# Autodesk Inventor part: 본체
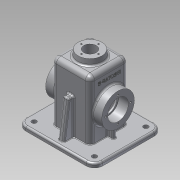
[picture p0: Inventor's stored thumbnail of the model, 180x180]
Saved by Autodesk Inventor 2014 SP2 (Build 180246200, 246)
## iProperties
Created: 2016-08
Part Number: 본체
Material: 알루미늄 6061
Document SubType Name: Modeling
Designer: user
Density: 2.71 g/cm^3
Appearance: 알루미늄 - 평지
Author: user
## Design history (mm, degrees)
sketch "스케치4"
  geometry: L1 (-65, 57.5)-(65, 57.5); L2 (65, 57.5)-(65, -57.5); L3 (65, -57.5)-(-65, -57.5); L4 (-65, -57.5)-(-65, 57.5); L5 (-65, 57.5)-(65, -57.5); L6 (65, 57.5)-(-65, -57.5); 1 further point
  constraints: 12 end point, 2 midpoint, 2 parallel, 1 horizontal, 1 perpendicular
  dimensions: "d11" = 130 distance of L1.start L1.end; "d12" = 115 distance of L1.end L2.end
extrude "돌출3" new body sketch "스케치4" distance "d13" = 10; taper "d14" = 0 deg
sketch "스케치5"
  geometry: L1 (-32.5, -32.5)-(32.5, -32.5); L2 (32.5, -32.5)-(32.5, 32.5); L3 (32.5, 32.5)-(-32.5, 32.5); L4 (-32.5, 32.5)-(-32.5, -32.5); L5 (-32.5, -32.5)-(32.5, 32.5); L6 (32.5, -32.5)-(-32.5, 32.5); 1 further point
  constraints: 12 end point, 2 midpoint, 2 parallel, 1 horizontal, 1 perpendicular
  dimensions: "d15" = 65 distance of L3.end L2.end; "d16" = 65 distance of L2.end L1.end
extrude "돌출4" join sketch "스케치5" distance "d17" = 100; taper "d18" = 0 deg
sketch "스케치6"
  geometry: L1 (0, 110)-(0, 120); L2 (0, 120)-(-20, 120); L3 (-20, 120)-(-21.228, 110); L4 (-32.5, 110)-(32.5, 110) reference; L5 (65, 0)-(-65, 0) reference; 1 further point
  constraints: 6 end point, 1 midpoint, 1 perpendicular, 1 point on line, 1 vertical
  dimensions: "d19" = 20 distance of L1.end L2.end; "d20" = 97 deg angle of L4 L3; "d21" = 120 distance between parallel lines of L5 L2
revolve "회전1" sketch "스케치6" stored, may be unused: angle "d22" = 90 deg
sketch "스케치7"
  geometry: C1 r 27.5 at (0, 55); 1 further point
  constraints: 1 centre point, 1 vertical alignment
  dimensions: "d23" = 55 diameter of C1; "d24" = 55 distance of point (0, 0) C1.centre
extrude "돌출5" join sketch "스케치7" stored distance "d25" = 95; taper "d26" = 0 deg
sketch "스케치8"
  geometry: L1 (27.5, -27.5)-(-27.5, -27.5); L2 (-27.5, -27.5)-(-27.5, 27.5); L3 (-27.5, 27.5)-(27.5, 27.5); L4 (27.5, 27.5)-(27.5, -27.5); L5 (27.5, -27.5)-(-27.5, 27.5); L6 (-27.5, -27.5)-(27.5, 27.5); 1 further point
  constraints: 12 end point, 2 midpoint, 2 parallel, 1 horizontal, 1 perpendicular
  dimensions: "d27" = 55 distance of L2.end L3.end; "d28" = 55 distance of L1.end L2.end
extrude "돌출6" cut sketch "스케치8" distance "d29" = 105; taper "d30" = 0 deg
hole "구멍1" diameter "d33" = 21; stored, may be unused: countersink angle "d37" = 90 deg, drill point angle "d39" = 118 deg; dims "d31" = 10, "d32" = 10, "d34" = 6, "d35" = 4, "d36" = 2, "d38" = 8
hole "구멍2" diameter "d42" = 35; stored, may be unused: countersink angle "d46" = 90 deg, drill point angle "d48" = 0 deg; dims "d43" = 6, "d44" = 4, "d45" = 2, "d47" = 17, "d58" = 10, "d59" = 10
hole "구멍3" diameter "d51" = 35; stored, may be unused: countersink angle "d55" = 90 deg, drill point angle "d57" = 0 deg; dims "d52" = 6, "d53" = 4, "d54" = 2, "d56" = 17, "d60" = 10, "d61" = 10
hole "구멍4" diameter "d64" = 30; stored, may be unused: countersink angle "d68" = 90 deg, drill point angle "d70" = 118 deg; dims "d62" = 10, "d63" = 10, "d65" = 6, "d66" = 4, "d67" = 2, "d69" = 3
hole "구멍5" diameter "d73" = 30; stored, may be unused: countersink angle "d77" = 90 deg, drill point angle "d79" = 118 deg; dims "d71" = 10, "d72" = 10, "d74" = 6, "d75" = 4, "d76" = 2, "d78" = 3
sketch "스케치9"
  geometry: 5 further points
  constraints: 1 horizontal alignment, 1 vertical alignment
  dimensions: "d80" = 102 distance of point (51, 43.5) point (-51, 43.5); "d81" = 87 distance of point (51, -43.5) point (51, 43.5); "d82" = 87 distance of point (-51, -43.5) point (-51, 43.5); "d83" = 102 distance of point (51, -43.5) point (-51, -43.5); "d84" = 51 horizontal distance of point (-51, -43.5) point (0, 0) (= 0.5 x d83); "d85" = 43.5 vertical distance of point (-51, -43.5) point (0, 0) (= 0.5 x d82)
hole "구멍6" sketch "스케치9" at (-51, 43.5), (51, 43.5), (51, -43.5), (-51, -43.5) diameter "d86" = 8; stored, may be unused: countersink angle "d90" = 90 deg, drill point angle "d92" = 118 deg; dims "d87" = 6, "d88" = 4, "d89" = 2, "d91" = 3
sketch "스케치10"
  geometry: L1 (-65, -57.5)-(65, -57.5) reference; L2 (65, -57.5)-(65, 57.5) reference; L3 (-65, 57.5)-(-65, -57.5) reference; L4 (65, 57.5)-(-65, 57.5) reference; L5 (60, -52.5)-(-60, -52.5); L6 (-60, -52.5)-(-60, 52.5); L7 (-60, 52.5)-(60, 52.5); L8 (60, 52.5)-(60, -52.5); 1 further point
  constraints: 8 end point, 3 other
  dimensions: "d93" = 5 distance between parallel lines of L1 L5
extrude "돌출7" cut sketch "스케치10" distance "d94" = 3; taper "d95" = 0 deg
fillet "모깎기1" dims "d96" = 14
sketch "스케치11"
  geometry: L1 (-42.5, 3)-(-27.5, 3); L2 (-27.5, 3)-(-27.5, -3); L3 (-27.5, -3)-(-42.5, -3); L4 (-42.5, -3)-(-42.5, 3); L5 (-42.5, 3)-(-27.5, -3); L6 (-27.5, 3)-(-42.5, -3); L7 (27.5, 3)-(42.5, 3); L8 (42.5, 3)-(42.5, -3); L9 (42.5, -3)-(27.5, -3); L10 (27.5, -3)-(27.5, 3); L11 (27.5, 3)-(42.5, -3); L12 (42.5, 3)-(27.5, -3); L13 (-27.5, 27.5)-(-27.5, -27.5) reference; L14 (27.5, -27.5)-(27.5, 27.5) reference; 7 further points
  constraints: 24 end point, 10 midpoint, 4 parallel, 2 horizontal, 2 horizontal alignment, 2 perpendicular
  dimensions: "d97" = 15 distance of L2.end L3.end; "d98" = 6 distance of L1.end L2.end; "d99" = 15 distance of L8.end L9.end; "d100" = 6 distance of L7.end L8.end
extrude "돌출8" join sketch "스케치11" stored distance "d101" = 3; taper "d102" = 0 deg
sketch "스케치12"
  geometry: C1 r 17.5 at (0, 0) reference; 2 further points
  constraints: 1 horizontal alignment
  dimensions: "d103" = 21 distance of C1.centre point (-21, 0)
hole "구멍7" sketch "스케치12" at (-21, 0) diameter "d104" = 3.242; stored, may be unused: countersink angle "d108" = 90 deg, drill point angle "d110" = 118 deg; dims "d105" = 8, "d106" = 4, "d107" = 2, "d109" = 10
fillet "모깎기2" dims "d114" = 8
sketch "스케치13"
  geometry: L1 (-41.068, 70)-(-49.5, 10); L2 (-39.5, 0)-(-47.5, 0) reference; L3 (-57.5, 10)-(-43.5, 10) reference; L4 (-57.5, 3)-(-57.5, 10) reference; L5 (-41.068, 70)-(-32.5, 70); L6 (-32.5, 10)-(-32.5, 102) reference; L7 (43.5, 10)-(-43.5, 10) reference; 1 further point
  constraints: 4 end point, 2 point on line, 1 perpendicular
  dimensions: "d115" = 70 distance from line of L2 L1.start; "d116" = 98 deg angle of L3 L1; "d117" = 8 distance from line of L4 L1.end
feature "리브1" sketch "스케치13" dims "d118" = 1, "d119" = 10, "d120" = 0, "d121" = 0, "d122" = 1, "d123" = 1
fillet "모깎기3" dims "d124" = 0.3
sketch "스케치14"
  geometry: 2 further points
  constraints: 1 vertical alignment
  dimensions: "d125" = 14.5 distance of point (0, 0) point (0, 14.5)
hole "구멍8" sketch "스케치14" at (0, 14.5) diameter "d126" = 2.459; stored, may be unused: countersink angle "d130" = 90 deg, drill point angle "d132" = 118 deg; dims "d127" = 7, "d128" = 4, "d129" = 2, "d131" = 9
fillet "모깎기4" dims "d136" = 3
fillet "모깎기5" dims "d137" = 3
fillet "모깎기8" dims "d140" = 3
fillet "모깎기9" dims "d141" = 3
fillet "모깎기10" dims "d142" = 1
fillet "모깎기11" dims "d143" = 9
sketch "스케치15"
  geometry: L1 (0, -8)-(91, -8) reference; L2 (-18, 44.5)-(-18, 4.5) reference; 2 further points
  constraints: 1 other
  dimensions: "d144" = 32.5 distance from line of L1 point (8, 24.5); "d145" = 26 distance from line of point (8, 24.5) L2
feature "엠보싱1" sketch "스케치15" dims "d69" = 3, "d134" = 360 deg, "d146" = 0.5, "d147" = 0
fillet "모깎기12" dims "d148" = 3
fillet "모깎기13" dims "d149" = 3
node "솔리드2"
pattern_circular "원형 패턴1" dims angle "d112" = 360 deg
mirror "대칭1"
mirror "대칭2"
pattern_circular "원형 패턴2" dims angle "d134" = 360 deg
